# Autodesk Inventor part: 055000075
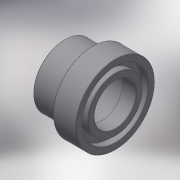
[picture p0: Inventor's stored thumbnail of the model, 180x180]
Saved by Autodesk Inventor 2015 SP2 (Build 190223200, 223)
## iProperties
Created: 2017-10
Part Number: 055000075
Material: Generic
Description: PLASSON FLANGE AD.+O-RING-CE 75
Document SubType Name: Modeling
Designer: KIM
Density: 1 g/cm^3
Appearance: Default
Author: KIM
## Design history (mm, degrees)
derived "055000.ipt"
feature "Solid1::055000.ipt"
tag "TaggingFeature1"
body "Solid1"
other parameters: "d0" = 53, "d1" = 88, "d2" = 75, "d3" = 67.5, "d4" = 15, "d5" = 44, "d6" = 106, "d8" = 4.5, "d11" = 0.75, "d12" = 4.5, "d15" = 5.775, "d_" = 75, "E_" = 88, "E_1" = 106, "l_" = 44, "B_" = 15, "H_" = 53, "d14" = 19.25
